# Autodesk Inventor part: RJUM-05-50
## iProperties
Author: Malcolm
Shininess: 31.0
PropertySet Name: _Private Model Information
Created: 2001-03
Part Number: RJUM-05-50
Description: DryLin Short Housing
Document SubType Name: Modeling
Designer: Malcolm
Control State: 0
Master: False
Checked Out: False
PropertySet Name: Design Tracking Control
Density: 0.0
Volumn: 0.0
Area: 0.0
PropertySet Name: Model Information
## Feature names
1. Revolution1
2. Extrusion1
3. Circular Pattern1
4. Extrusion2
5. Revolution2
6. Extrusion6
7. Chamfer3
8. Hole3
9. Hole6
10. Hole4
